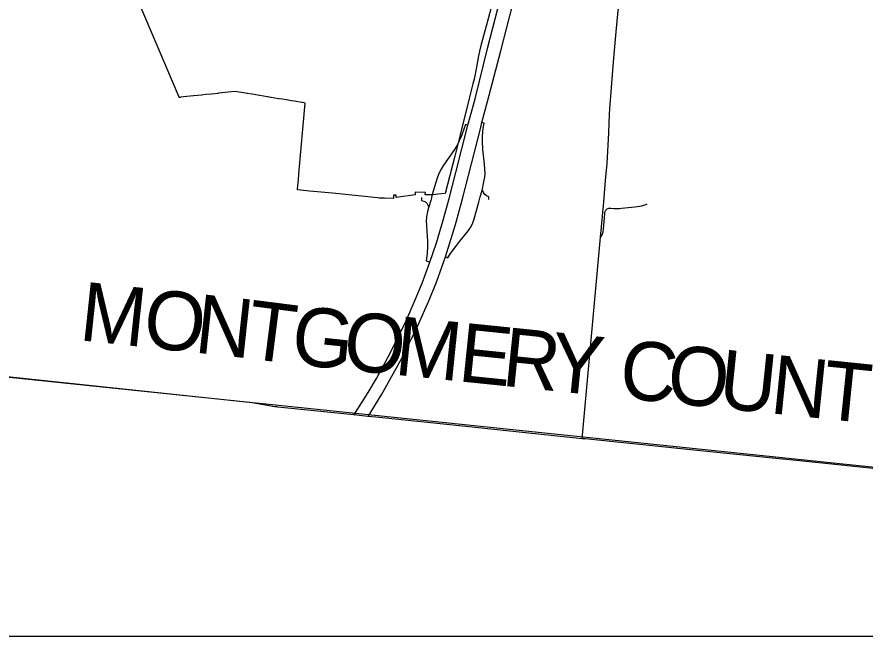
# Model space of a CAD drawing. Extents: x 0 to 34, y 0 to 22.
# Drawn here: x 4.9537 to 5.1855, y 14.1 to 14.2693 of the extents above; entities that cross this region are included whole.
import ezdxf

# ---------------------------------------------------------------- set-up
doc = ezdxf.new("R2010")
doc.units = 0
for name, color, linetype in [('GM_X_Corporation', 7, 'Continuous'), ('GM_X_County', 7, 'Continuous'), ('GM_X_County_Text', 7, 'Continuous'), ('GM_X_Interchange_Ramps', 7, 'Continuous'), ('GM_X_Interstate_Route', 7, 'Continuous'), ('GM_X_State_Route', 7, 'Continuous'), ('SC_Scratch1', 7, 'Continuous'), ('SH_Data', 7, 'Continuous')]:
    doc.layers.add(name, color=color, linetype=linetype)

msp = doc.modelspace()

# ---------------------------------------------------------------- linework, layer by layer
at = {"layer": 'GM_X_Corporation'}
msp.add_lwpolyline([(5.083842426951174, 14.273905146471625), (5.081903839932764, 14.266766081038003), (5.081521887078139, 14.265359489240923), (5.080569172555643, 14.26185101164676), (5.080096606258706, 14.259923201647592), (5.080072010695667, 14.259822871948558), (5.079848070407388, 14.25867388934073), (5.079839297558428, 14.25862885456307), (5.0792475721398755, 14.255592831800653), (5.078606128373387, 14.252301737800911), (5.078280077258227, 14.25101147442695), (5.07726519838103, 14.246995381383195), (5.077259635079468, 14.246973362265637), (5.074850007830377, 14.237023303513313), (5.073340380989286, 14.23118629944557), (5.070684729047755, 14.221014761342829), (5.068736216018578, 14.220805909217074), (5.067417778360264, 14.220667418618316), (5.065237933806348, 14.220665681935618), (5.065330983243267, 14.221325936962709), (5.062543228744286, 14.221338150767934), (5.062481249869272, 14.220687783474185), (5.057347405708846, 14.219944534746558), (5.057345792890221, 14.220581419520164), (5.056549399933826, 14.220570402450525), (5.056551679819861, 14.21968568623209), (5.054128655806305, 14.219697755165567), (5.05364975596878, 14.21970831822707), (5.053345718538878, 14.219723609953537), (5.053034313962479, 14.21973989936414), (5.052638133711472, 14.219766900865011), (5.052189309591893, 14.219805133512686), (5.040841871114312, 14.2209751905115), (5.036826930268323, 14.221380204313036), (5.03366338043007, 14.221638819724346), (5.032001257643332, 14.221817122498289), (5.0303676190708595, 14.222021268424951), (5.030384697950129, 14.222218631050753), (5.030394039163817, 14.222326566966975), (5.0305999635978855, 14.22470575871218), (5.030749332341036, 14.226431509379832), (5.03242164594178, 14.245752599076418), (5.031703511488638, 14.245857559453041), (5.0317045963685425, 14.24586462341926), (5.031510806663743, 14.245896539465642), (5.031457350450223, 14.245905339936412), (5.029528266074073, 14.246223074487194), (5.029474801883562, 14.246231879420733), (5.028735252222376, 14.246353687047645), (5.028681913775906, 14.246362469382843), (5.027308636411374, 14.246588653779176), (5.027261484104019, 14.246596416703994), (5.026261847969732, 14.246761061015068), (5.026213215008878, 14.246769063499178), (5.025230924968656, 14.246930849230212), (5.025182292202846, 14.246938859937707), (5.024184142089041, 14.247103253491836), (5.0241355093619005, 14.247111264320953), (5.023153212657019, 14.247273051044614), (5.023104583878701, 14.247281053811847), (5.022106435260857, 14.247445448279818), (5.022057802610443, 14.247453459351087), (5.02107551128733, 14.24761523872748), (5.021026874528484, 14.247623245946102), (5.020028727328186, 14.247787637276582), (5.01998008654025, 14.247795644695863), (5.018997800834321, 14.247957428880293), (5.0189491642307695, 14.247965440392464), (5.0179510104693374, 14.248129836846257), (5.017902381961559, 14.248137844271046), (5.016643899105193, 14.24834508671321), (5.01660061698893, 14.248352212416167), (5.016096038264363, 14.248435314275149), (5.013285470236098, 14.248898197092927), (5.011438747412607, 14.248702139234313), (5.008804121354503, 14.248422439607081), (5.008734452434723, 14.24841504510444), (5.008590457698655, 14.248399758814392), (5.006837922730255, 14.24821371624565), (5.006780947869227, 14.248207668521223), (5.005290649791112, 14.248049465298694), (5.0052455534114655, 14.248044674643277), (5.004077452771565, 14.247920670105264), (5.0040367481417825, 14.247916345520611), (5.003038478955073, 14.247810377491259), (5.002997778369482, 14.247806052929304), (5.001999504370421, 14.247700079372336), (5.00195880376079, 14.247695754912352), (4.999170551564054, 14.247399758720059), (4.998467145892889, 14.247325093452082), (4.998439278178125, 14.247322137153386), (4.998337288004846, 14.247311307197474), (4.998280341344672, 14.247305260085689), (4.998037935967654, 14.24727953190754), (4.9980180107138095, 14.247326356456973), (4.986802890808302, 14.273682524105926)], dxfattribs=at)
at = {"layer": 'GM_X_County'}
msp.add_lwpolyline([(5.19105433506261, 14.145467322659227), (5.17815238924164, 14.146790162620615), (5.166631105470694, 14.147971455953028), (5.161104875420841, 14.148537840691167), (5.139590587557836, 14.150743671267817), (5.108966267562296, 14.153883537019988), (5.108172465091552, 14.153964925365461), (5.107380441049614, 14.154047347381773), (5.0729196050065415, 14.157633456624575), (5.051743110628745, 14.159837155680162), (5.049621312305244, 14.160057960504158), (5.04570617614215, 14.16046535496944), (5.0249840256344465, 14.162621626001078), (5.024822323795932, 14.162638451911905), (5.024115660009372, 14.162712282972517), (5.017995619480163, 14.163757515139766), (4.929360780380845, 14.173144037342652)], dxfattribs=at)
at = {"layer": 'GM_X_Interchange_Ramps'}
for points in [[(5.080988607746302, 14.233635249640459), (5.080940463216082, 14.234659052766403), (5.080921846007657, 14.236446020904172), (5.081014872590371, 14.238046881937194), (5.081201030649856, 14.239294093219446), (5.081424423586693, 14.240262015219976), (5.080782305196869, 14.240385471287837)], [(5.076958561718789, 14.239690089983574), (5.076245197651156, 14.239900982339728), (5.075797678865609, 14.238595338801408), (5.0753695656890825, 14.237310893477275), (5.075034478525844, 14.236361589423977), (5.074494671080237, 14.235207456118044), (5.074154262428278, 14.234558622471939)], [(5.074154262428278, 14.234558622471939), (5.073898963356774, 14.234071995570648), (5.07304273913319, 14.232768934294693), (5.070306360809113, 14.228766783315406), (5.069599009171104, 14.227668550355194)], [(5.0801441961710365, 14.219385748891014), (5.080329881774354, 14.220121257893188), (5.080804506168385, 14.221820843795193), (5.081331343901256, 14.224197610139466), (5.081517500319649, 14.225482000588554), (5.081647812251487, 14.226468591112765), (5.081591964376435, 14.227622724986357), (5.081498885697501, 14.229056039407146), (5.0810148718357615, 14.233076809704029), (5.080988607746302, 14.233635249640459)], [(5.069599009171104, 14.227668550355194), (5.068984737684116, 14.226458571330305), (5.06842626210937, 14.224932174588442), (5.067125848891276, 14.220705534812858)], [(5.082672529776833, 14.21932810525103), (5.082687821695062, 14.220136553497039), (5.082044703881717, 14.220335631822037), (5.081585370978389, 14.220718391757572), (5.0811719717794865, 14.22130023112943), (5.081049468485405, 14.221774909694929), (5.080804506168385, 14.221820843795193)], [(5.064256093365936, 14.219876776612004), (5.06426669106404, 14.219051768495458), (5.0648960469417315, 14.218945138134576), (5.065322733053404, 14.21871045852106), (5.0656961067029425, 14.218369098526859), (5.065962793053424, 14.217846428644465), (5.066048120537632, 14.217441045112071), (5.06628902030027, 14.217370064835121)], [(5.066981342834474, 14.219838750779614), (5.066788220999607, 14.219063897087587), (5.06628902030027, 14.217370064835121), (5.065898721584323, 14.216045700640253), (5.065605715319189, 14.214650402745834), (5.065535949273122, 14.21342249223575), (5.065591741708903, 14.21233417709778), (5.065603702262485, 14.212157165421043)], [(5.067125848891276, 14.220705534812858), (5.067044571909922, 14.220441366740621), (5.066981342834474, 14.219838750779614)], [(5.078453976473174, 14.2135368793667), (5.078635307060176, 14.214048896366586), (5.079902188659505, 14.218603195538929), (5.0801441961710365, 14.219385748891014)], [(5.113185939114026, 14.209095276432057), (5.113509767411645, 14.209544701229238), (5.113771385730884, 14.210015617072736), (5.113893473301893, 14.210486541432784), (5.113980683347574, 14.21121908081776), (5.114155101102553, 14.213329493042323), (5.114329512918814, 14.215405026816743), (5.114364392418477, 14.215705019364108), (5.114397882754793, 14.215880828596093), (5.114464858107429, 14.216098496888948), (5.114540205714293, 14.21625756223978), (5.114632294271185, 14.216408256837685), (5.114757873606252, 14.216567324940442), (5.114891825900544, 14.216692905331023), (5.115042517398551, 14.216801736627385), (5.115235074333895, 14.216893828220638), (5.11545274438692, 14.2169608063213), (5.1156787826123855, 14.216969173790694), (5.1160220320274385, 14.216960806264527), (5.116834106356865, 14.21693568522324), (5.117713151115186, 14.216910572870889), (5.11817360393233, 14.216910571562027), (5.118508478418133, 14.216927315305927), (5.118960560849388, 14.216977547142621), (5.119831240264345, 14.217078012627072), (5.122610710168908, 14.217387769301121), (5.12380788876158, 14.217546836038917), (5.12447764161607, 14.21766404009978), (5.125005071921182, 14.217789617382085), (5.12542366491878, 14.217948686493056), (5.125910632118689, 14.21819206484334)], [(5.077296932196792, 14.211181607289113), (5.077781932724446, 14.211979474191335), (5.07827264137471, 14.213024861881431), (5.078453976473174, 14.2135368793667)], [(5.065603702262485, 14.212157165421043), (5.065801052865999, 14.209236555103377), (5.065870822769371, 14.207938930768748), (5.0658708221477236, 14.206473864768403), (5.0657591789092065, 14.204576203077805), (5.065494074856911, 14.202622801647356), (5.066564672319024, 14.20225649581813)], [(5.073513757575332, 14.206383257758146), (5.07387776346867, 14.206859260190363), (5.0747525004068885, 14.207989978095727), (5.076011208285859, 14.20952608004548), (5.07712056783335, 14.2108914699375), (5.077296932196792, 14.211181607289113)], [(5.07078763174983, 14.203715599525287), (5.071488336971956, 14.203403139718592), (5.072171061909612, 14.204576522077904), (5.073045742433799, 14.205771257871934), (5.073513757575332, 14.206383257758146)]]:
    msp.add_lwpolyline(points, dxfattribs=at)
at = {"layer": 'GM_X_Interstate_Route'}
for points in [[(5.07078763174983, 14.203715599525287), (5.073535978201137, 14.2125255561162), (5.075439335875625, 14.219517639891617), (5.080344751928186, 14.238717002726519), (5.080782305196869, 14.240385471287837), (5.082299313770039, 14.246144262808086), (5.085891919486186, 14.260049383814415), (5.09318887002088, 14.288418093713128), (5.09735856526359, 14.304575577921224), (5.101453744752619, 14.320007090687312)], [(5.045725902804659, 14.160420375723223), (5.04967747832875, 14.166620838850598), (5.051911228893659, 14.170432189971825), (5.055707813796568, 14.177374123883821), (5.060045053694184, 14.186197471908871), (5.062558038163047, 14.191949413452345), (5.064438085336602, 14.196491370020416), (5.066564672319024, 14.20225649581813), (5.068379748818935, 14.207518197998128), (5.070197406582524, 14.21368485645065), (5.071786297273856, 14.219656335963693), (5.073643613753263, 14.226715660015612), (5.076958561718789, 14.239690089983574), (5.078902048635, 14.246932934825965), (5.082392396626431, 14.261035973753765), (5.089745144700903, 14.289646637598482)], [(5.049641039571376, 14.160012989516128), (5.053436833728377, 14.166168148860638), (5.0592632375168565, 14.176629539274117), (5.063432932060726, 14.185248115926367), (5.066225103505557, 14.19165155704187), (5.0683099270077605, 14.19677055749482), (5.0699107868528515, 14.201163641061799), (5.07078763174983, 14.203715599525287)]]:
    msp.add_lwpolyline(points, dxfattribs=at)
at = {"layer": 'GM_X_State_Route'}
for p, q in [((5.114054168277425, 14.218688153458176), (5.114581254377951, 14.224536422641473)), ((5.113439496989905, 14.211896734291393), (5.114054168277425, 14.218688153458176))]:
    msp.add_line(p, q, dxfattribs=at)
for points in [[(5.114581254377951, 14.224536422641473), (5.1150045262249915, 14.229232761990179), (5.115486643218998, 14.237562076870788), (5.115654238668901, 14.242716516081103), (5.115700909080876, 14.244150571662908), (5.116584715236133, 14.254649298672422), (5.116956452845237, 14.259099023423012), (5.1174685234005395, 14.265228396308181), (5.1179238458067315, 14.27002243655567), (5.118459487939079, 14.274736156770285), (5.119605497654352, 14.283340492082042), (5.120393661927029, 14.289900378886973)], [(5.108192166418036, 14.153919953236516), (5.113185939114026, 14.209095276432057), (5.113439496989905, 14.211896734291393)]]:
    msp.add_lwpolyline(points, dxfattribs=at)
at = {"layer": 'SC_Scratch1'}
msp.add_lwpolyline([(5.5712702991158, 14.106219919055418), (4.853299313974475, 14.180865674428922), (3.9803362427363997, 14.19875001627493)], dxfattribs=at)
at = {"layer": 'SH_Data'}
msp.add_line((2.1, 14.1), (8.9, 14.1), dxfattribs=at)

# ---------------------------------------------------------------- texts
at = {"layer": 'GM_X_County_Text'}
for s, height, rotation, p in [('M', 0.016074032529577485, 353.896972, (4.970373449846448, 14.180927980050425)), ('O', 0.016074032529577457, 353.890367, (4.987743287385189, 14.17907075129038)), ('N', 0.016074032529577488, 353.766683, (5.001869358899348, 14.177558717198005)), ('T', 0.016074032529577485, 352.708498, (5.0159231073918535, 14.176024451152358)), ('G', 0.016074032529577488, 353.97398699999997, (5.028234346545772, 14.1744536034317)), ('O', 0.016074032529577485, 354.127015, (5.042418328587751, 14.172956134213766)), ('M', 0.016074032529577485, 354.132278, (5.0565609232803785, 14.171501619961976)), ('E', 0.016074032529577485, 354.134003, (5.073939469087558, 14.169715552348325)), ('R', 0.016074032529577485, 354.134731, (5.085899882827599, 14.168486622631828)), ('Y', 0.016074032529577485, 354.133059, (5.09891556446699, 14.16714952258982)), ('C', 0.01607403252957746, 354.134585, (5.117912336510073, 14.165197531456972)), ('O', 0.016074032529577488, 354.13414, (5.130928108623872, 14.163860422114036)), ('U', 0.016074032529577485, 354.133059, (5.145069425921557, 14.162407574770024)), ('N', 0.016074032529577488, 354.13433399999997, (5.159211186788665, 14.160954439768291)), ('T', 0.016074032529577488, 354.13346, (5.173352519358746, 14.159501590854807))]:
    msp.add_text(s, height=height, rotation=rotation, dxfattribs=at).set_placement(p)

doc.saveas('drawing.dxf')
